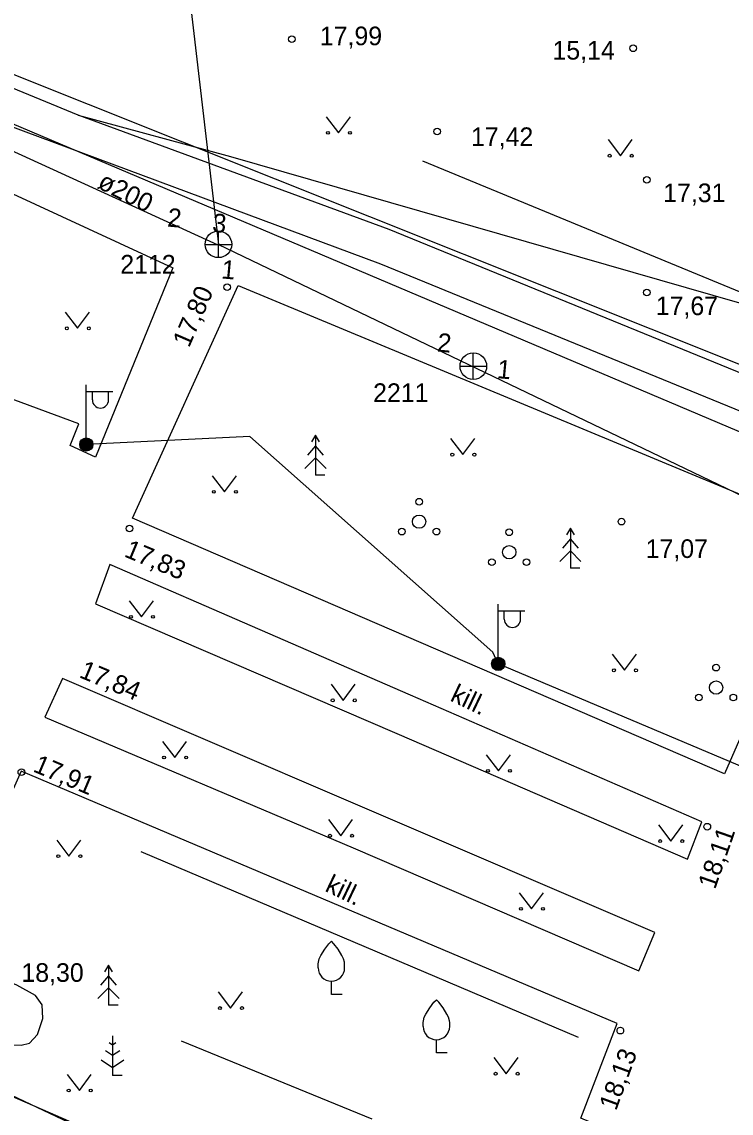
# Model space of a CAD drawing. Extents: x 713497 to 713863, y 6590062 to 6590327.
# Drawn here: x 713596.25 to 713622.93, y 6590260.04 to 6590301.08 of the extents above; entities that cross this region are included whole.
import ezdxf

# ---------------------------------------------------------------- set-up
doc = ezdxf.new("R2010")
doc.units = 0
for name, color, linetype in [('HALJASTUS', 7, 'Continuous'), ('KKAEV', 7, 'Continuous'), ('KORGUS', 7, 'Continuous'), ('KTRASS', 7, 'Continuous'), ('MPKAABEL', 7, 'Continuous'), ('POST', 7, 'Continuous'), ('PUU', 7, 'Continuous'), ('SIKAEV', 7, 'Continuous'), ('SITRASS', 7, 'Continuous'), ('TEE', 7, 'Continuous'), ('TORU NR', 7, 'Continuous'), ('TTRASS', 7, 'Continuous')]:
    doc.layers.add(name, color=color, linetype=linetype)

msp = doc.modelspace()

# ---------------------------------------------------------------- linework, layer by layer
at = {"layer": 'HALJASTUS'}
for p, q in [((713607.697, 6590297.507), (713608.16, 6590296.9)), ((713608.16, 6590296.9), (713608.606, 6590297.507)), ((713618.297, 6590296.647), (713618.76, 6590296.04)), ((713618.76, 6590296.04), (713619.206, 6590296.647)), ((713597.877, 6590290.157), (713598.34, 6590289.55)), ((713598.34, 6590289.55), (713598.786, 6590290.157)), ((713612.377, 6590285.407), (713612.84, 6590284.8)), ((713612.84, 6590284.8), (713613.286, 6590285.407)), ((713603.407, 6590284.007), (713603.87, 6590283.4)), ((713603.87, 6590283.4), (713604.316, 6590284.007)), ((713600.287, 6590279.307), (713600.75, 6590278.7)), ((713600.75, 6590278.7), (713601.196, 6590279.307)), ((713618.457, 6590277.297), (713618.92, 6590276.69)), ((713618.92, 6590276.69), (713619.366, 6590277.297)), ((713607.877, 6590276.167), (713608.34, 6590275.56)), ((713608.34, 6590275.56), (713608.786, 6590276.167)), ((713601.537, 6590274.017), (713602, 6590273.41)), ((713602, 6590273.41), (713602.446, 6590274.017)), ((713613.717, 6590273.517), (713614.18, 6590272.91)), ((713614.18, 6590272.91), (713614.626, 6590273.517)), ((713607.777, 6590271.077), (713608.24, 6590270.47)), ((713608.24, 6590270.47), (713608.686, 6590271.077)), ((713620.197, 6590270.877), (713620.66, 6590270.27)), ((713620.66, 6590270.27), (713621.106, 6590270.877)), ((713597.557, 6590270.307), (713598.02, 6590269.7)), ((713598.02, 6590269.7), (713598.466, 6590270.307)), ((713614.957, 6590268.327), (713615.42, 6590267.72)), ((713615.42, 6590267.72), (713615.866, 6590268.327)), ((713603.637, 6590264.597), (713604.1, 6590263.99)), ((713604.1, 6590263.99), (713604.546, 6590264.597)), ((713614.007, 6590262.127), (713614.47, 6590261.52)), ((713614.47, 6590261.52), (713614.916, 6590262.127)), ((713597.947, 6590261.497), (713598.41, 6590260.89)), ((713598.41, 6590260.89), (713598.856, 6590261.497))]:
    msp.add_line(p, q, dxfattribs=at)
for points in [[(713625.25, 6590290.1), (713611.33, 6590295.84)], [(713617.19, 6590262.88), (713600.73, 6590269.86)], [(713594.42, 6590262.88), (713594.76, 6590262.73), (713595.24, 6590262.64), (713595.8, 6590262.61), (713596.22, 6590262.59), (713596.53, 6590262.67), (713596.84, 6590263), (713597.04, 6590263.6), (713597.01, 6590264.11), (713596.76, 6590264.46), (713596.06, 6590264.85), (713595.16, 6590265.21), (713594.55, 6590265.25), (713594.07, 6590265.1), (713593.54, 6590264.83), (713593.22, 6590264.53), (713593.18, 6590264.28), (713593.18, 6590264.04), (713593.24, 6590263.78), (713593.34, 6590263.66), (713593.9, 6590263.23), (713594.43, 6590262.9)], [(713609.43, 6590259.81), (713602.25, 6590262.75)]]:
    msp.add_lwpolyline(points, dxfattribs=at)
for centre, radius in [((713607.759, 6590296.9), 0.055), ((713608.588, 6590296.9), 0.055), ((713618.359, 6590296.04), 0.055), ((713619.188, 6590296.04), 0.055), ((713597.939, 6590289.55), 0.055), ((713598.768, 6590289.55), 0.055), ((713612.439, 6590284.8), 0.055), ((713613.268, 6590284.8), 0.055), ((713603.469, 6590283.4), 0.055), ((713604.298, 6590283.4), 0.055), ((713611.19, 6590283.03), 0.125), ((713611.19, 6590282.28), 0.25), ((713610.54, 6590281.905), 0.125), ((713611.84, 6590281.905), 0.125), ((713614.58, 6590281.88), 0.125), ((713614.58, 6590281.13), 0.25), ((713613.93, 6590280.755), 0.125), ((713615.23, 6590280.755), 0.125), ((713600.349, 6590278.7), 0.055), ((713601.178, 6590278.7), 0.055), ((713618.519, 6590276.69), 0.055), ((713619.348, 6590276.69), 0.055), ((713622.36, 6590276.79), 0.125), ((713622.36, 6590276.04), 0.25), ((713607.939, 6590275.56), 0.055), ((713608.768, 6590275.56), 0.055), ((713621.71, 6590275.665), 0.125), ((713623.01, 6590275.665), 0.125), ((713601.599, 6590273.41), 0.055), ((713602.428, 6590273.41), 0.055), ((713613.779, 6590272.91), 0.055), ((713614.608, 6590272.91), 0.055), ((713607.839, 6590270.47), 0.055), ((713608.668, 6590270.47), 0.055), ((713620.259, 6590270.27), 0.055), ((713621.088, 6590270.27), 0.055), ((713597.619, 6590269.7), 0.055), ((713598.448, 6590269.7), 0.055), ((713615.019, 6590267.72), 0.055), ((713615.848, 6590267.72), 0.055), ((713603.699, 6590263.99), 0.055), ((713604.528, 6590263.99), 0.055), ((713614.069, 6590261.52), 0.055), ((713614.898, 6590261.52), 0.055), ((713598.009, 6590260.89), 0.055), ((713598.838, 6590260.89), 0.055)]:
    msp.add_circle(centre, radius, dxfattribs=at)
at = {"layer": 'KKAEV'}
for p, q in [((713603.64, 6590292.208), (713603.64, 6590293.208)), ((713603.14, 6590292.708), (713604.14, 6590292.708)), ((713613.23, 6590287.625), (713613.23, 6590288.625)), ((713612.73, 6590288.125), (713613.73, 6590288.125))]:
    msp.add_line(p, q, dxfattribs=at)
for centre in [(713603.64, 6590292.708), (713613.23, 6590288.125)]:
    msp.add_circle(centre, 0.5, dxfattribs=at)
at = {"layer": 'KORGUS'}
for centre in [(713606.4, 6590300.42), (713619.24, 6590300.08), (713611.87, 6590296.95), (713619.76, 6590295.13), (713603.97, 6590291.1), (713619.76, 6590290.9), (713600.3, 6590282.02), (713618.8, 6590282.28), (713596.23, 6590272.86), (713622.03, 6590270.81), (713618.76, 6590263.14)]:
    msp.add_circle(centre, 0.125, dxfattribs=at)
at = {"layer": 'KTRASS'}
for points in [[(713601.258, 6590313.085), (713603.64, 6590292.708)], [(713603.627, 6590292.676), (713584.02, 6590301.64)], [(713603.64, 6590292.708), (713644.999, 6590272.866)]]:
    msp.add_lwpolyline(points, dxfattribs=at)
at = {"layer": 'MPKAABEL'}
for points in [[(713598.37, 6590297.57), (713587.28, 6590302.14), (713590.9, 6590311.18), (713582.74, 6590314.64)], [(713584.24, 6590314.87), (713592.08, 6590311.75), (713588.15, 6590302.22), (713637.53, 6590282.5), (713644.67, 6590279.58), (713658.61, 6590275.44), (713680.04, 6590269.22), (713682.53, 6590274.19), (713706.97, 6590264.14)], [(713699.54, 6590263.131), (713689.332, 6590266.147), (713666.709, 6590272.832), (713651.218, 6590277.42), (713642.378, 6590280.091), (713624.891, 6590287.217), (713610.06, 6590293.26), (713598.37, 6590297.57)], [(713598.37, 6590297.57), (713604.09, 6590296.01), (713644.48, 6590284.41), (713684.62, 6590274.96), (713706.75, 6590268.92)], [(713614.169, 6590276.931), (713613.967, 6590277.369), (713604.82, 6590285.482), (713598.672, 6590285.18)], [(713645.02, 6590263.908), (713614.169, 6590276.931)]]:
    msp.add_lwpolyline(points, dxfattribs=at)
at = {"layer": 'POST'}
for p, q in [((713598.672, 6590285.43), (713598.672, 6590287.43)), ((713598.672, 6590287.18), (713599.672, 6590287.18)), ((713598.899, 6590286.859), (713598.899, 6590287.18)), ((713599.511, 6590286.859), (713599.511, 6590287.18)), ((713614.169, 6590277.181), (713614.169, 6590279.181)), ((713614.169, 6590278.931), (713615.169, 6590278.931)), ((713614.396, 6590278.61), (713614.396, 6590278.931)), ((713615.008, 6590278.61), (713615.008, 6590278.931))]:
    msp.add_line(p, q, dxfattribs=at)
for centre, radius in [((713598.672, 6590285.18), 0.25), ((713598.672, 6590285.18), 0.225), ((713598.672, 6590285.18), 0.2), ((713598.672, 6590285.18), 0.175), ((713598.672, 6590285.18), 0.15), ((713598.672, 6590285.18), 0.125), ((713598.672, 6590285.18), 0.1), ((713598.672, 6590285.18), 0.075), ((713598.672, 6590285.18), 0.05), ((713598.672, 6590285.18), 0.025), ((713614.169, 6590276.931), 0.25), ((713614.169, 6590276.931), 0.225), ((713614.169, 6590276.931), 0.2), ((713614.169, 6590276.931), 0.175), ((713614.169, 6590276.931), 0.15), ((713614.169, 6590276.931), 0.125), ((713614.169, 6590276.931), 0.1), ((713614.169, 6590276.931), 0.075), ((713614.169, 6590276.931), 0.05), ((713614.169, 6590276.931), 0.025)]:
    msp.add_circle(centre, radius, dxfattribs=at)
for centre in [(713599.205, 6590286.859), (713614.702, 6590278.61)]:
    msp.add_arc(centre, 0.306, 180, 0, dxfattribs=at)
at = {"layer": 'PUU'}
for p, q in [((713607.29, 6590285.53), (713607.14, 6590285.28)), ((713607.44, 6590285.28), (713607.29, 6590285.53)), ((713607.29, 6590285.53), (713607.29, 6590284.03)), ((713607.29, 6590285.13), (713606.99, 6590284.78)), ((713607.59, 6590284.78), (713607.29, 6590285.13)), ((713607.29, 6590284.68), (713606.89, 6590284.28)), ((713607.69, 6590284.28), (713607.29, 6590284.68)), ((713607.65, 6590284.03), (713607.29, 6590284.03)), ((713616.88, 6590282.03), (713616.73, 6590281.78)), ((713617.03, 6590281.78), (713616.88, 6590282.03)), ((713616.88, 6590282.03), (713616.88, 6590280.53)), ((713616.88, 6590281.63), (713616.58, 6590281.28)), ((713617.18, 6590281.28), (713616.88, 6590281.63)), ((713616.88, 6590281.18), (713616.48, 6590280.78)), ((713617.28, 6590280.78), (713616.88, 6590281.18)), ((713617.24, 6590280.53), (713616.88, 6590280.53)), ((713599.51, 6590265.6), (713599.36, 6590265.35)), ((713599.66, 6590265.35), (713599.51, 6590265.6)), ((713599.51, 6590265.6), (713599.51, 6590264.1)), ((713599.51, 6590265.2), (713599.21, 6590264.85)), ((713599.81, 6590264.85), (713599.51, 6590265.2)), ((713607.89, 6590264.5), (713607.89, 6590265)), ((713599.51, 6590264.75), (713599.11, 6590264.35)), ((713599.91, 6590264.35), (713599.51, 6590264.75)), ((713608.29, 6590264.5), (713607.89, 6590264.5)), ((713599.87, 6590264.1), (713599.51, 6590264.1)), ((713599.66, 6590262.95), (713599.66, 6590261.45)), ((713611.84, 6590262.3), (713611.84, 6590262.8)), ((713599.66, 6590262.2), (713599.393, 6590262.378)), ((713599.66, 6590262.6), (713599.536, 6590262.683)), ((713599.784, 6590262.683), (713599.66, 6590262.6)), ((713599.927, 6590262.378), (713599.66, 6590262.2)), ((713599.236, 6590262.039), (713599.66, 6590261.757)), ((713599.66, 6590261.757), (713600.084, 6590262.039)), ((713612.24, 6590262.3), (713611.84, 6590262.3)), ((713600.02, 6590261.45), (713599.66, 6590261.45))]:
    msp.add_line(p, q, dxfattribs=at)
for points in [[(713607.39, 6590265.5), (713607.39, 6590265.65), (713607.4, 6590265.715), (713607.435, 6590265.845), (713607.495, 6590265.965), (713607.64, 6590266.2), (713607.8, 6590266.405), (713607.89, 6590266.5)], [(713608.39, 6590265.5), (713608.39, 6590265.65), (713608.38, 6590265.715), (713608.345, 6590265.845), (713608.285, 6590265.965), (713608.14, 6590266.2), (713607.98, 6590266.405), (713607.89, 6590266.5)], [(713611.34, 6590263.3), (713611.34, 6590263.45), (713611.35, 6590263.515), (713611.385, 6590263.645), (713611.445, 6590263.765), (713611.59, 6590264), (713611.75, 6590264.205), (713611.84, 6590264.3)], [(713612.34, 6590263.3), (713612.34, 6590263.45), (713612.33, 6590263.515), (713612.295, 6590263.645), (713612.235, 6590263.765), (713612.09, 6590264), (713611.93, 6590264.205), (713611.84, 6590264.3)]]:
    msp.add_lwpolyline(points, dxfattribs=at)
for centre in [(713607.89, 6590265.5), (713611.84, 6590263.3)]:
    msp.add_arc(centre, 0.5, 180, 0, dxfattribs=at)
at = {"layer": 'SITRASS'}
msp.add_lwpolyline([(713624.63, 6590285.07), (713590.38, 6590299.57)], dxfattribs=at)
at = {"layer": 'TEE'}
for points in [[(713647.964, 6590276.295), (713647.189, 6590279.23), (713645.489, 6590278.482), (713644.073, 6590277.883), (713636.133, 6590281.17), (713609.749, 6590291.956), (713590.7, 6590299.05), (713592.2, 6590295.73)], [(713670.756, 6590228.07), (713634.678, 6590243.788), (713580.049, 6590267.542), (713581.278, 6590270.224), (713582.538, 6590273.183), (713586.336, 6590281.535), (713592.563, 6590296.145)], [(713592.563, 6590296.145), (713601.93, 6590291.83), (713599.012, 6590284.7), (713598.07, 6590285.149), (713598.387, 6590285.961), (713595.29, 6590287.098), (713594.96, 6590286.133), (713594.048, 6590286.449), (713592.574, 6590286.177), (713591.001, 6590285.886), (713590.549, 6590284.92), (713589.797, 6590285.271), (713588.899, 6590283.294), (713587.424, 6590283.905)], [(713604.39, 6590291.157), (713642.016, 6590275.519), (713637.118, 6590271.215), (713624.427, 6590276.787), (713622.677, 6590272.791), (713600.415, 6590282.415), (713604.39, 6590291.157)], [(713599.559, 6590280.663), (713599.016, 6590279.194), (713610.352, 6590274.314), (713621.287, 6590269.584), (713621.82, 6590270.998), (713610.867, 6590275.753), (713599.559, 6590280.663)], [(713597.779, 6590276.38), (713597.117, 6590274.928), (713608.713, 6590270.018), (713619.461, 6590265.384), (713620.058, 6590266.826), (713608.889, 6590271.616), (713597.779, 6590276.38)], [(713631.759, 6590245.03), (713630.049, 6590254.438), (713617.269, 6590259.855), (713618.646, 6590263.406), (713596.22, 6590272.9), (713591.585, 6590262.502)]]:
    msp.add_lwpolyline(points, dxfattribs=at)
at = {"layer": 'TTRASS'}
msp.add_lwpolyline([(713582.143, 6590267.213), (713612.417, 6590252.868), (713616.413, 6590250.919), (713630.042, 6590244.273), (713670.551, 6590224.518), (713678.954, 6590220.421)], dxfattribs=at)

# ---------------------------------------------------------------- texts
at = {"layer": 'KORGUS'}
for s, p in [('17,99', (713607.456, 6590300.195)), ('15,14', (713616.208, 6590299.655)), ('17,42', (713613.143, 6590296.405)), ('17,31', (713620.372, 6590294.295)), ('17,67', (713620.093, 6590290.045)), ('17,07', (713619.713, 6590280.915)), ('18,30', (713596.231, 6590264.975))]:
    msp.add_text(s, height=0.7, dxfattribs=at).set_placement(p)
for s, rotation, p in [('17,80', 66.5635, (713602.536, 6590288.795)), ('17,83', 337.3016, (713600.061, 6590280.981)), ('17,84', 337.3016, (713598.367, 6590276.44)), ('17,91', 337.017, (713596.632, 6590272.897)), ('18,11', 70.8219, (713622.322, 6590268.425)), ('18,13', 69.9401, (713618.599, 6590260.101))]:
    msp.add_text(s, height=0.7, rotation=rotation, dxfattribs=at).set_placement(p)
at = {"layer": 'SIKAEV'}
for s, p in [('2112', (713599.95, 6590291.61)), ('2211', (713609.46, 6590286.78))]:
    msp.add_text(s, height=0.7, dxfattribs=at).set_placement(p)
at = {"layer": 'TEE'}
for p in [(713612.322, 6590275.563), (713607.612, 6590268.403)]:
    msp.add_text('kill.', height=0.7, rotation=334.4912, dxfattribs=at).set_placement(p)
at = {"layer": 'TORU NR'}
for s, rotation, p in [('ø200', 332.9695, (713599.049, 6590294.851)), ('2', 354.7103, (713601.701, 6590293.38)), ('3', 354.7103, (713603.391, 6590293.18)), ('1', 354.7103, (713603.731, 6590291.43)), ('2', 354.7103, (713611.851, 6590288.68)), ('1', 354.7103, (713614.101, 6590287.68))]:
    msp.add_text(s, height=0.7, rotation=rotation, dxfattribs=at).set_placement(p)

doc.saveas('drawing.dxf')
